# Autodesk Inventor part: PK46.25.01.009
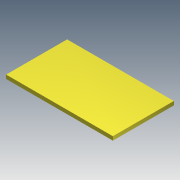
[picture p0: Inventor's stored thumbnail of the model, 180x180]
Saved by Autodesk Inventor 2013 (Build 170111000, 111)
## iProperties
Created: 2005-04
Part Number: PK46.25.01.009
Material: Steel, Mild
Document SubType Name: Modeling
Designer: salex
Manufacturer: Standard
Standards Organization: Custom
Density: 7.86 g/cm^3
Mass: 3521.28 g
Surface Area: 984 cm^2
Volume: 448 cm^3
Author: salex
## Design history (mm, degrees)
sketch "Эскиз1"
  geometry: L1 (0, 0)-(280, 0); L2 (280, 0)-(280, 160); L3 (280, 160)-(0, 160); L4 (0, 160)-(0, 0)
  constraints: 8 end point, 2 parallel, 1 horizontal, 1 perpendicular, 1 other
  dimensions: "d0" = 160 distance of L3.end L1.start; "d1" = 280 distance of L1.start L1.end
extrude "Выдавливание1" new body sketch "Эскиз1" distance "d2" = 10; taper "d3" = 0 deg
body "Solid1"
